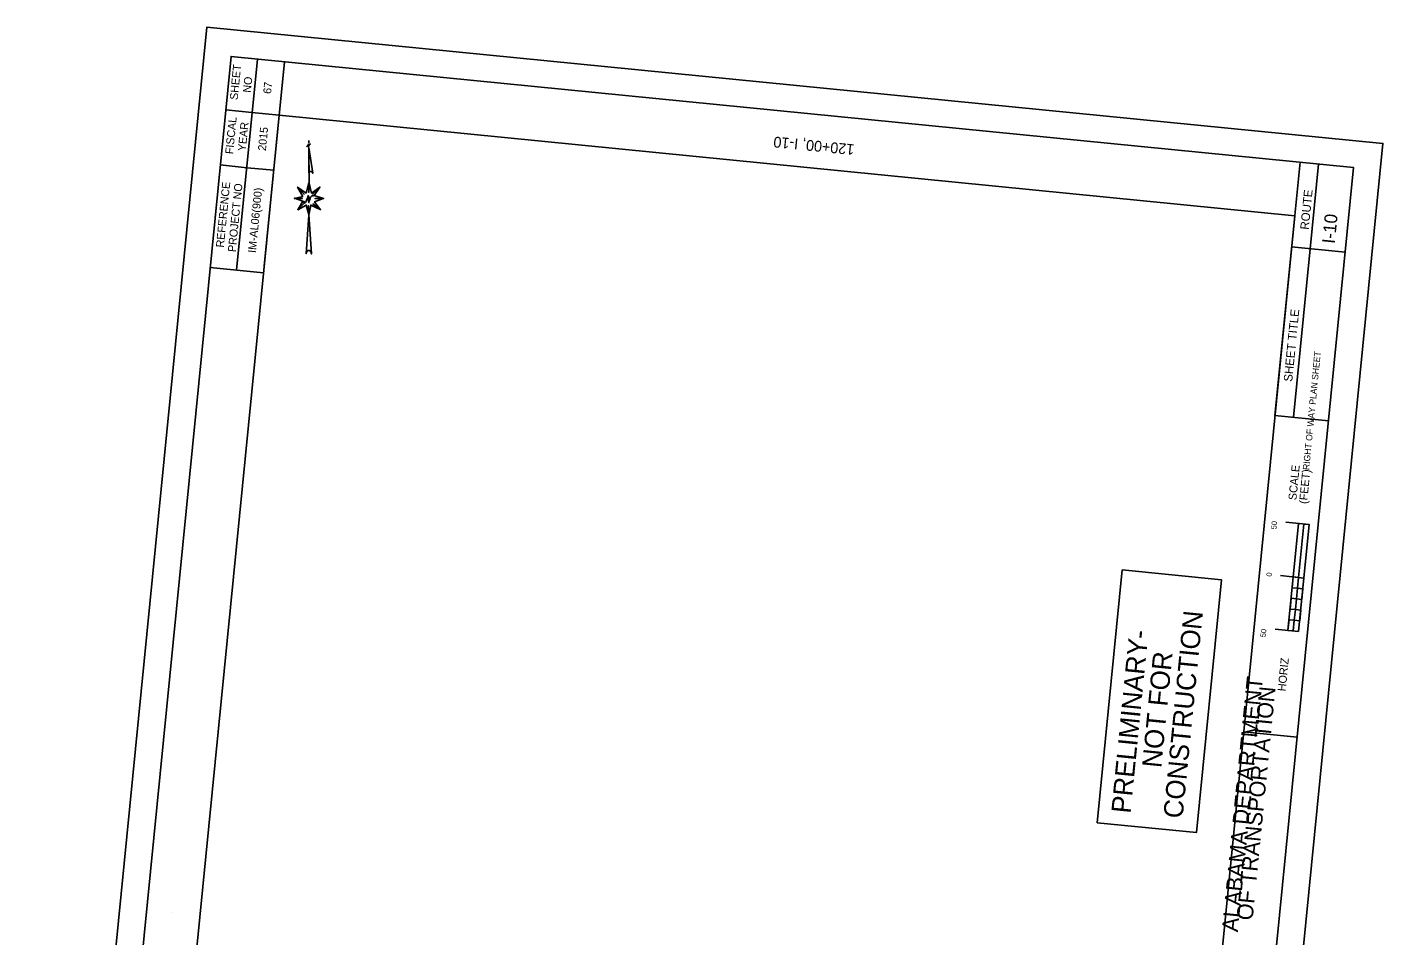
# Model space of a CAD drawing. Extents: x 1796928 to 1798191, y 245238 to 247038.
# Drawn here: x 1796928 to 1798191, y 246192 to 247038 of the extents above; entities that cross this region are included whole.
import ezdxf

# ---------------------------------------------------------------- set-up
doc = ezdxf.new("R2010")
doc.units = 0
for name, color, linetype in [('1', 7, 'Continuous'), ('ANNO-SHT', 7, 'Continuous'), ('ANNO-SYMB', 7, 'Continuous'), ('ANNO-TXT', 7, 'Continuous'), ('DRAINAGE', 7, 'Continuous'), ('Level 1', 7, 'Continuous'), ('Level 57', 7, 'Continuous'), ('Level 6', 7, 'Continuous'), ('Level 62', 7, 'Continuous'), ('SHT-BDR', 7, 'Continuous'), ('SHT-BNDRY', 7, 'Continuous')]:
    doc.layers.add(name, color=color, linetype=linetype)

# ---------------------------------------------------------------- blocks, each defined once
blk = doc.blocks.new('SC47208')
at = {"layer": 'Level 1'}
blk.add_line((0, 0), (0, 0), dxfattribs=at)

msp = doc.modelspace()

# ---------------------------------------------------------------- linework, layer by layer
at = {"layer": '1'}
msp.add_lwpolyline([(1797924.7, 246297.1), (1797948, 246532.4), (1798040.2, 246523.3), (1798016.9, 246288)], close=True, dxfattribs=at)
at = {"layer": 'ANNO-SYMB'}
for p, q in [((1798122, 246574.6), (1798100.1, 246576.8)), ((1798112, 246575.6), (1798102.2, 246476.1)), ((1798122, 246574.6), (1798112.1, 246475.1)), ((1798122, 246574.6), (1798117, 246575.1)), ((1798122, 246574.6), (1798117, 246575.1)), ((1798122, 246574.6), (1798117, 246575.1)), ((1798117, 246524.9), (1798095.2, 246527.1)), ((1798117, 246524.9), (1798095.2, 246527.1)), ((1798117, 246524.9), (1798095.2, 246527.1)), ((1798112.1, 246525.4), (1798107.1, 246525.9)), ((1798112.1, 246525.4), (1798107.1, 246525.9)), ((1798112.1, 246525.4), (1798107.1, 246525.9)), ((1798112.1, 246525.4), (1798110.1, 246505.5)), ((1798108.1, 246485.6), (1798103.2, 246486.1)), ((1798108.1, 246485.6), (1798103.2, 246486.1)), ((1798112.1, 246475.1), (1798090.2, 246477.3))]:
    msp.add_line(p, q, dxfattribs=at)
for points in [[(1798112.1, 246525.4), (1798117, 246575.1), (1798122, 246574.6), (1798117, 246524.9)], [(1798106.1, 246515.9), (1798107.1, 246525.9), (1798112.1, 246525.4), (1798111.1, 246515.4)], [(1798104.1, 246496), (1798105.1, 246506), (1798110.1, 246505.5), (1798109.1, 246495.5)], [(1798110.1, 246505.5), (1798111.1, 246515.4), (1798116.1, 246514.9), (1798115.1, 246505)], [(1798108.1, 246485.6), (1798109.1, 246495.5), (1798114.1, 246495), (1798113.1, 246485.1)], [(1798102.2, 246476.1), (1798103.2, 246486.1), (1798108.1, 246485.6), (1798107.1, 246475.6)]]:
    msp.add_lwpolyline(points, close=True, dxfattribs=at)
at = {"layer": 'ANNO-TXT'}
for p, q in [((1798122.9, 246831.4), (1798130.7, 246910.1)), ((1798107.4, 246674.5), (1798122.9, 246831.4))]:
    msp.add_line(p, q, dxfattribs=at)
at = {"layer": 'Level 57'}
msp.add_line((1797190.8, 246932.2), (1797190.7, 246929.8), dxfattribs=at)
for points in [[(1797191.9, 246928.7), (1797191.8, 246928.6), (1797191.9, 246928.5), (1797192, 246928.6), (1797192, 246928.8), (1797191.7, 246928.8), (1797191.5, 246928.7), (1797191.3, 246928.5), (1797191.1, 246928.2), (1797191, 246927.8), (1797190.8, 246927.2), (1797190.7, 246927), (1797190.6, 246926.6), (1797190.6, 246927.2), (1797190.6, 246928.2), (1797190.4, 246928.8), (1797190.4, 246928.2), (1797190.6, 246926.6), (1797190.6, 246928.2), (1797190.4, 246928.8), (1797190.2, 246928.2), (1797189.9, 246927.2), (1797189.6, 246926.6), (1797189.3, 246926.6), (1797189.1, 246926.6), (1797189, 246926.6), (1797189, 246926.8), (1797189.1, 246926.9), (1797189.2, 246926.9), (1797189.1, 246926.7)], [(1797190.7, 246925.7), (1797194.4, 246901.6), (1797194.2, 246902.3), (1797194, 246902.6), (1797193.6, 246903), (1797193.1, 246903.2), (1797192.8, 246903.3), (1797192.4, 246903.3), (1797192, 246903.3), (1797191.8, 246903.2), (1797191.4, 246903), (1797191.1, 246902.8), (1797190.9, 246902.5), (1797190.8, 246902.2), (1797190.7, 246902.1), (1797190.7, 246925.5), (1797190.9, 246892.6)], [(1797190.8, 246892.6), (1797190.6, 246883.7), (1797190.8, 246892.7), (1797188.1, 246883.1), (1797180.2, 246888.7), (1797186.3, 246882), (1797180.2, 246888.7), (1797185.1, 246880.1), (1797177.1, 246878.2), (1797184.8, 246878), (1797177.3, 246878.3), (1797185, 246875.5), (1797180.4, 246867.7), (1797186.2, 246873.4), (1797180.4, 246867.7), (1797188.3, 246872), (1797190.6, 246863.1), (1797190.5, 246871.5), (1797190.6, 246862.9), (1797192.6, 246871.9), (1797201.6, 246867.8), (1797192.5, 246871.9), (1797190.6, 246862.7), (1797188.3, 246826.7), (1797188.5, 246827.8), (1797188.8, 246828.6), (1797189.3, 246829.1), (1797189.9, 246829.6), (1797190.4, 246829.7), (1797191.1, 246829.7), (1797191.6, 246829.5), (1797192.1, 246829.2), (1797192.5, 246828.7), (1797192.9, 246828), (1797193, 246827.5), (1797193.2, 246826.6), (1797190.7, 246863.2), (1797192.5, 246872), (1797201.4, 246867.8), (1797194.6, 246873.1), (1797201.3, 246868), (1797196.1, 246875), (1797204.1, 246878.1), (1797196.5, 246878), (1797204.4, 246878.1), (1797195.6, 246880.8), (1797201.1, 246888.7), (1797194.6, 246882.3), (1797201.1, 246888.7), (1797193.1, 246883.1), (1797190.9, 246892.5)], [(1797194.6, 246880.6), (1797194.4, 246880.4), (1797194.7, 246880.2), (1797194.9, 246880.5), (1797194.8, 246880.9), (1797194.7, 246881), (1797194, 246880.9), (1797193.4, 246880.7), (1797192.4, 246879.4), (1797192.3, 246879), (1797191.9, 246877.8), (1797191.5, 246876.5), (1797191, 246875.7), (1797190.8, 246874.3), (1797190.8, 246876), (1797190.6, 246878.3), (1797190.5, 246879.5), (1797190, 246880.9), (1797190, 246879.2), (1797190.3, 246876.9), (1797190.5, 246875.5), (1797190.8, 246874.3), (1797190.8, 246876.4), (1797190.6, 246879.5), (1797190, 246880.9), (1797189.7, 246879.4), (1797189.1, 246877.8), (1797188.8, 246877.2), (1797188.5, 246876.3), (1797188.1, 246875.6), (1797187.8, 246875.1), (1797187.6, 246874.5), (1797186.8, 246874.1), (1797186.1, 246874.3), (1797185.9, 246874.5), (1797185.8, 246875.2), (1797186.2, 246875.5), (1797186.5, 246875.2), (1797186.3, 246874.9)]]:
    msp.add_lwpolyline(points, dxfattribs=at)
at = {"layer": 'Level 6'}
for p, q in [((1797142.9, 247007.8), (1797123.5, 246811.5)), ((1797168, 247005.4), (1797149.2, 246815)), ((1797137.6, 246958.1), (1797113.4, 246960.5)), ((1797137.6, 246958.1), (1797163.1, 246955.6)), ((1797133.2, 246906.8), (1797108.3, 246909.3)), ((1798113.4, 246911.8), (1798090.1, 246676.3)), ((1797133.2, 246906.8), (1797158, 246904.4)), ((1797098.9, 246813.9), (1797148.6, 246809))]:
    msp.add_line(p, q, dxfattribs=at)
at = {"layer": 'Level 62'}
msp.add_lwpolyline([(1798023.1, 245237.6), (1798190.5, 246929.3), (1797095.9, 247037.6), (1796928.5, 245345.9)], close=True, dxfattribs=at)
at = {"layer": 'SHT-BDR'}
msp.add_lwpolyline([(1797960.8, 245369.3), (1798108.5, 246862), (1797163.1, 246955.6), (1797015.4, 245462.9)], close=True, dxfattribs=at)
at = {"layer": 'SHT-BNDRY'}
for p, q in [((1798155.4, 246828.2), (1798105.6, 246833.1)), ((1798139.9, 246671.3), (1798090.1, 246676.3)), ((1798110.8, 246376.8), (1798060.9, 246381.7))]:
    msp.add_line(p, q, dxfattribs=at)
msp.add_lwpolyline([(1798004.4, 245302.2), (1798163.2, 246906.9), (1797118.3, 247010.3), (1796959.5, 245405.6)], close=True, dxfattribs=at)

# ---------------------------------------------------------------- block references
at = {"layer": 'DRAINAGE', "xscale": 1.0000020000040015, "yscale": 1.0000020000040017, "rotation": -32.06753455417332}
msp.add_blockref('SC47208', (1797063.6, 246213.4), dxfattribs=at)
msp.add_blockref('SC47208', (1797063.6, 246213.4), dxfattribs=at)

# ---------------------------------------------------------------- texts
at = {"layer": '1'}
for s, p in [('CONSTRUCTION', (1798004, 246300.6)), ('PRELIMINARY-', (1797955.6, 246305.3)), ('NOT FOR', (1797984.2, 246347.7))]:
    msp.add_text(s, height=18, rotation=84.3491, dxfattribs=at).set_placement(p)
at = {"layer": 'ANNO-SHT'}
for s, height, rotation, p in [('67', 7.45, 84.3491, (1797155.6, 246975.2)), ('2015', 7.45, 84.3491, (1797150.7, 246922.2)), ('120+00, I-10', 10, 174.3491, (1797698.9, 246928.4)), ('IM-AL06(900)', 7.449, 84.3491, (1797141.4, 246827.2)), ('  I-10  ', 12, 84.3491, (1798144.9, 246826.8)), ('               RIGHT OF WAY PLAN SHEET               ', 6, 84.3491, (1798118.6, 246591.9))]:
    msp.add_text(s, height=height, rotation=rotation, dxfattribs=at).set_placement(p)
at = {"layer": 'ANNO-SYMB'}
for s, height, p in [('SCALE', 7.5, (1798110, 246597.1)), ('(FEET)', 7.5, (1798119.9, 246593.6)), (' 50', 5, (1798091.2, 246568.1)), ('0', 5, (1798087, 246526)), ('0', 5, (1798087, 246526)), ('0', 5, (1798087, 246526)), (' 50', 5, (1798081.2, 246467.7)), ('HORIZ', 7.5, (1798100, 246419.2))]:
    msp.add_text(s, height=height, rotation=84.4063, dxfattribs=at).set_placement(p)
at = {"layer": 'ANNO-TXT'}
for s, height, p in [('ROUTE', 8, (1798121.5, 246848.8)), ('SHEET TITLE', 8, (1798106.1, 246707.3)), ('ALABAMA DEPARTMENT', 15, (1798055.5, 246195)), ('OF TRANSPORTATION', 15, (1798069.2, 246205.8))]:
    msp.add_text(s, height=height, rotation=84.3491, dxfattribs=at).set_placement(p)
at = {"layer": 'Level 6'}
for s, p in [('SHEET', (1797124.5, 246969.6)), ('NO', (1797136.7, 246976.3)), ('FISCAL', (1797120.2, 246919.1)), ('YEAR', (1797132, 246921.9)), ('REFERENCE', (1797111.6, 246832.2)), ('PROJECT NO', (1797122.7, 246828))]:
    msp.add_text(s, height=7.44, rotation=84.3491, dxfattribs=at).set_placement(p)

doc.saveas('drawing.dxf')
